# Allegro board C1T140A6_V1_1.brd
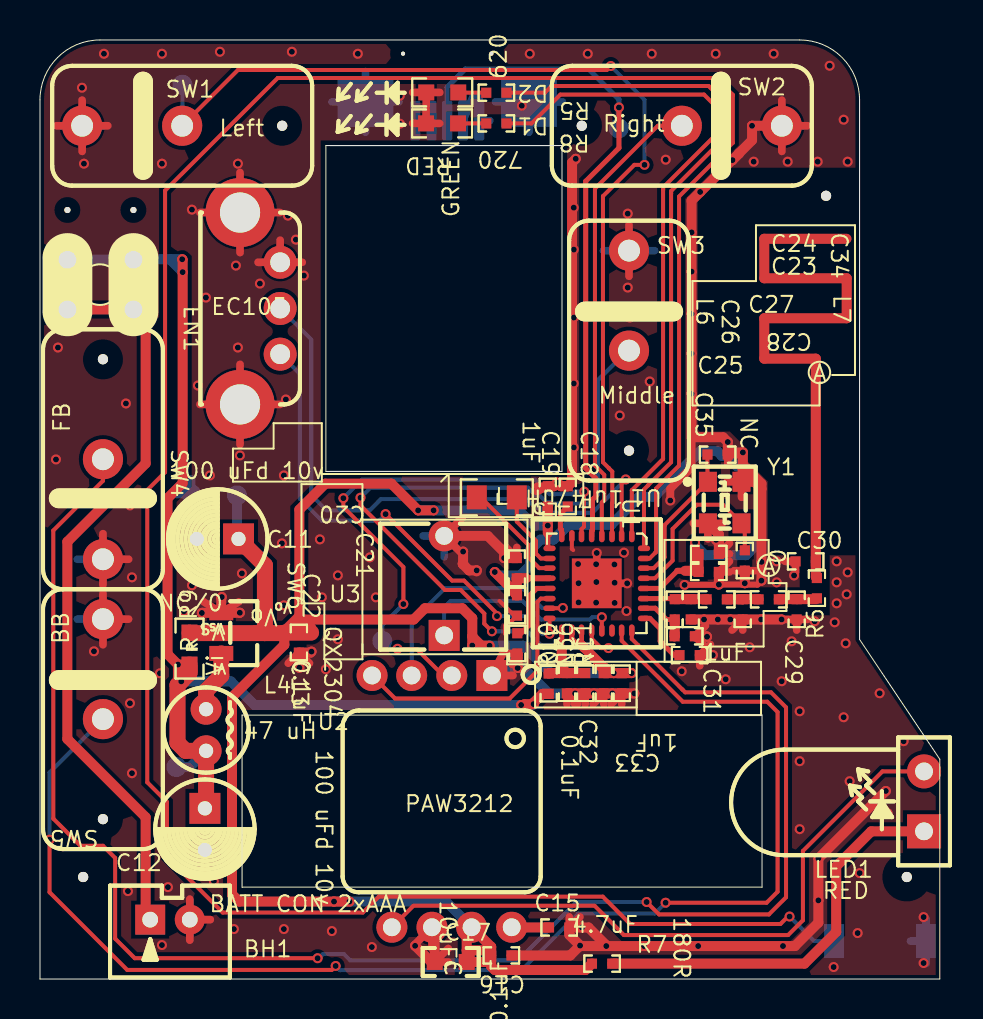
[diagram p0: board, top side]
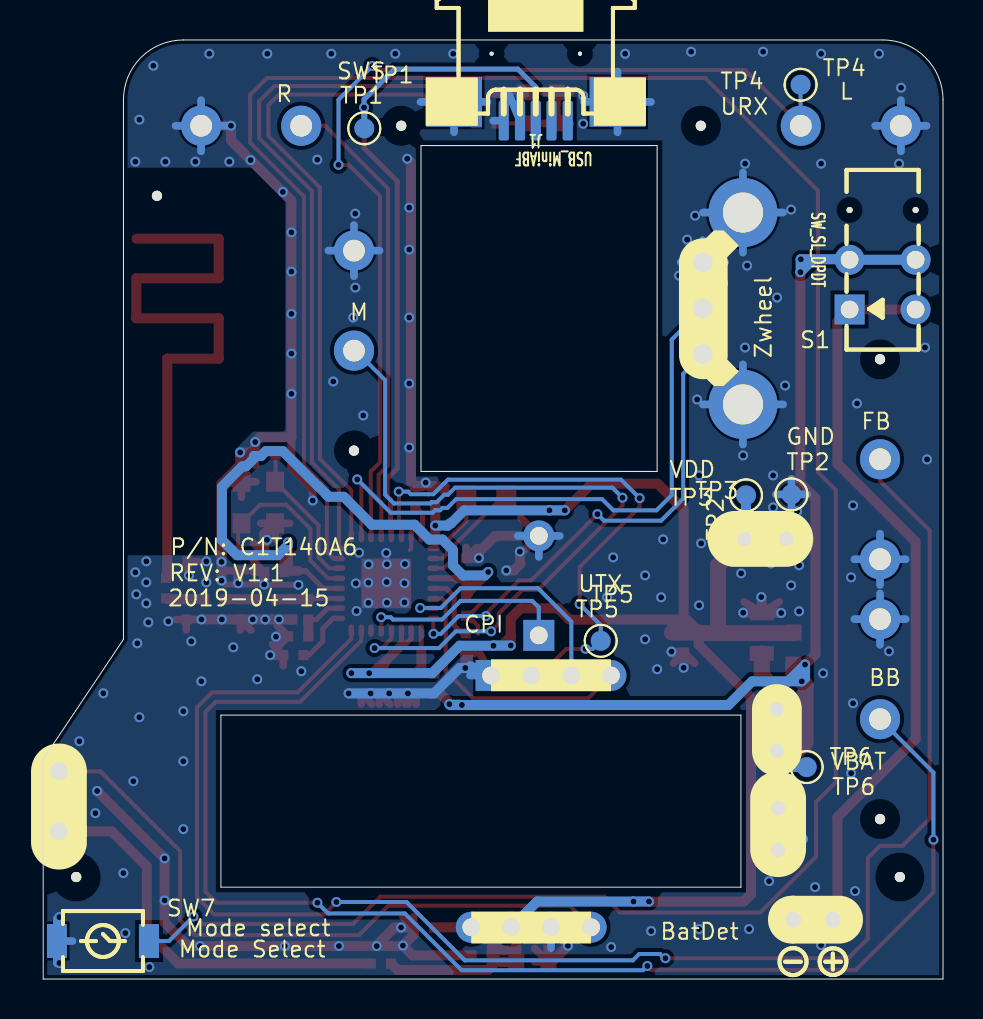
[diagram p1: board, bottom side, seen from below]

Outline 45.01 x 46.99 mm; copper layers: TOP, BOTTOM. Coordinates in mm from the lower left corner of the outline.
Outline path: 14.5,41.71 25.7,41.71 ; 25.91,25.4 14.5,25.4 ; 0,43.99 arc(0.88,46.11) 3,46.99 38,46.99 arc(40.12,46.11) 41,43.99 41,16.99 45.01,11 45.01,0 0,0 0,43.99 ; 10.11,13.21 36.12,13.21 36.12,4.6 10.11,4.6 10.11,13.21 ; 14.3,41.71 26.11,41.71 26.11,25.4 14.3,25.4 14.3,41.71

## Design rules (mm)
nets with their own width: nets AVDD GND LED N14408943 N14492061 VBAT ZWHEEL1 ZWHEEL2

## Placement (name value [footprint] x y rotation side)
BH1  BATT CON 2xAAA  [BATT-HDR200F-2PIN]  6.5 2.97 180 top
C11  100 uFd 10v  [C-100UF10V-ELECT]  8.89 22.02 180 top
C12  100 uFd 10v  [C-100UF10V-ELECT]  8.25 7.5 270 top
C13  0.1uF  [0402]  12.95 16.84 270 top
C15  4.7uF  [0402]  25.97 2.58 0 top
C16  0.1uF  [0402]  23.08 1.18 0 top
C17  10uF  [0603C]  20.54 0.85 180 top
C18  1uF  [0402]  26.4 24.15 270 top
C19  1uF  [0402]  25.4 24.15 270 top
C20  0.1uF  [0402]  23.85 20.56 270 top
C21  1uF  [0402]  23.86 18.69 90 top
C22  1uF  [0402]  23.87 16.79 90 top
C23  0.1uF  [0402]  33.45 20.37 0 top
C24  2.2uF  [0402]  33.45 21.27 0 top
C25  18pF  [0402]  32.25 17.15 180 top
C26  1.2pF  [0402]  32.55 18.5 270 top
C27  220pF  [0402]  33.85 19 180 top
C28  1.8pF  [0402]  35.15 18.5 270 top
C29  2.7pF  [0402]  37.85 18.5 270 top
C30  1pF  [0402]  38.3 20.9 180 top
C31  1uF  [0402]  32.49 16.21 180 top
C32  0.1uF  [0402]  28.2 14.8 90 top
C33  1uF  [0402]  29.1 14.8 90 top
C34  NC  [0402]  35.25 20.94 90 top
C35  NC  [0402]  33.9 26.24 0 top
C36  NC  [0402]  26.36 14.8 90 top
D1  GREEN  [0603-LED]  20.11 42.82 180 top
D2  RED  [0603-LED]  20.12 44.36 180 top
EN1  EC10E  [ENCODER-BTC-MOUSE]  12.01 35.87 90 top
J1  USB_MiniABF  [HIROSE-US60-MB-5ST_MINIUSB_7PIN]  20.37 52.3 0 bottom
L4  47 uH  [L-TH-IND2MM]  8.31 12.46 90 top
L5  47uH  [0805L]  22.85 24.1 0 top
L6  1.3nH  [0402]  31.75 18.5 90 top
L7  1.8nH  [0402]  36.45 19 0 top
LED1  RED  [LED_TH_3MM_2PIN]  44.22 8.89 90 top
NOREF  -  [unnamed]  43.36 5.11 0 top
NOREF#2  -  [unnamed]  2.16 5.11 0 top
NOREF#3  -  [unnamed]  39.32 39.19 0 top
R5  620  [0402]  22.83 44.35 0 top
R6  0  [0402]  38.86 19.56 90 top
R7  180R  [0402]  28.12 0.77 0 top
R8  720  [0402]  22.83 42.82 0 top
R9  NC/0  [0603R]  7.48 16.54 90 top
R10  0  [0402]  25.44 14.78 90 top
R11  NC  [0402]  27.27 14.8 270 top
S1  SW_SL_DPDT  [SW-TH-6PIN-3_60X9_00-34NP]  3.02 35.99 270 bottom
SW1  Left  [SW-CHICONY-MOUSE-3PIN-TH-3NP]  2.11 42.7 0 top
SW2  Right  [SW-CHICONY-MOUSE-3PIN-TH-3NP]  37.11 42.7 180 top
SW3  Middle  [SW-CHICONY-MOUSE-3PIN-TH-3NP]  29.46 36.45 270 top
SW4  FB  [SW-CHICONY-MOUSE-3PIN-TH-3NP]  3.15 21.01 90 top
SW5  BB  [SW-CHICONY-MOUSE-3PIN-TH-3NP]  3.15 18.01 270 top
SW6  CPI  [SW-MOUSE-2PIN-TH]  20.22 19.68 90 top
SW7  Mode select  [BUTSMD2PX4_00Y3_00_NH]  42.02 1.9 270 bottom
TP1  SWS  [TP100]  28.95 42.57 180 bottom
TP2  GND  [TP100]  7.58 24.25 180 bottom
TP3  VDD  [TP100]  9.86 24.2 180 bottom
TP4  URX  [TP100]  7.12 44.75 180 bottom
TP5  UTX  [TP100]  17.12 16.92 180 bottom
TP6  BatDet  [TP100]  6.82 10.61 180 bottom
U1  TLSR8258F512ET32  [QFN_5X5_32PIN_0P5_2P50X2P50]  27.85 19.8 270 top
U2  PAW3212  [SDIP8-ADNS5030]  20.6 8.89 180 top
U3  QX2304  [QX2304_SOT-23]  10.16 17.31 270 top
Y1  24MHz-12pF-+/-20ppm  [OSCCC200X250X080]  34.25 23.84 0 top

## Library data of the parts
BH1 = Chicony Battery conn 2xAA: User Part Number: pn; Tolerance: RichardLC
C11 C12 = 100 uFd Electrolytic 10v: User Part Number: partnum; Tolerance: RichardLC
C13 C16 = C1005X5R1C104K
C15 C18-C36 = C1005X5R1C105K
C17 = C1608X5R0J106M
D1 = 0603D_Green
D2 = 0603D_Red
EN1 = EC10E
J1 = USB_MiniABF_0: Tolerance: RichardLC; User Part Number: pn
L4 = 27 uH Inductor TH: User Part Number: partnum; Tolerance: RichardLC
L5-L7 = MLK1608_000R
LED1 = LED_5: User Part Number: partnum; Tolerance: RichardLC
R5 R6 R8 = RS0402K621JT
R7 R10 R11 = RS0402K181JT
R9 = RS0402K_34.8K_1%
S1 = SW_SL_DPDT: User Part Number: pn; Tolerance: RichardLC
SW1-SW5 = Switch Chicony Mouse 3PIN TH
SW6 = Switch Mouse Button 2PIN: Tolerance: RichardLC; User Part Number: partnum
SW7 = SW2PIN_3x4
TP1-TP6 = TestPad100
U1 = TLSR8258F512ET32
U2 = PAN3204UL
U3 = QX2304_SOT-23
Y1 = CRYSTAL4/SM_0

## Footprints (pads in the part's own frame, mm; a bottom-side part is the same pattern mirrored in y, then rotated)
0402
  rect 0.508x0.508 smd: 1(-0.508,0) 2(0.508,0)
0603-LED
  rect 0.8x0.8 smd: A(-0.8,0) C(0.8,0)
0603C
  rect 0.8x0.8 smd: 1(-0.8,0) 2(0.8,0)
0603R
  rect 0.8x0.8 smd: 1(-0.8,0) 2(0.8,0)
0805L
  rect 1x1.2 smd: 1(-1,0) 2(1,0)
BATT-HDR200F-2PIN
  rect 1.499x1.499 hole 0.787: 1(0.991,0)
  round 1.499 hole 0.787: 2(-0.991,0)
BUTSMD2PX4_00Y3_00_NH
  rect 1.7x1 smd: 1(0,2.3) 2(0,-2.3)
C-100UF10V-ELECT
  rect 1.549x1.549 hole 0.711: 1(-1.041,0)
  round 1.549 hole 0.711: 2(1.041,0)
ENCODER-BTC-MOUSE
  round 1.651 hole 0.991: 1(0,0) 2(-2.311,0) 3(-4.597,0)
  round 3.454 hole 2.007: 4(-7.112,2.007) 5(2.489,2.007)
HIROSE-US60-MB-5ST_MINIUSB_7PIN
  round 0.203 hole 0.889 unplated: (-2.21,5.994) (2.21,5.994)
  custom 0.127x0.127 smd: 1(-1.6,9.347) 2(-0.787,9.347) 3(0,9.347) 4(0.787,9.347) 5(1.6,9.347)
  rect 2.794x2.489 smd: 6(-4.089,8.407) 9(4.089,8.407)
L-TH-IND2MM
  round 1.549 hole 0.711: 1(-1.041,0) 2(1.041,0)
LED_TH_3MM_2PIN
  rect 1.702x1.702 hole 0.889: 1(-1.499,0)
  round 1.702 hole 0.889: 2(1.499,0)
OSCCC200X250X080
  rect 0.9x1 smd: 1(-0.84,1.04) 2(-0.84,-1.04) 3(0.84,-1.04) 4(0.84,1.04)
QFN_5X5_32PIN_0P5_2P50X2P50
  oval 0.61x0.279 smd: 1(-2.362,1.753) 2(-2.362,1.245) 3(-2.362,0.762) 4(-2.362,0.254) 5(-2.362,-0.254) 6(-2.362,-0.762) 7(-2.362,-1.245) 8(-2.362,-1.753) 17(2.362,-1.753) 18(2.362,-1.245) 19(2.362,-0.762) 20(2.362,-0.254) 21(2.362,0.254) 22(2.362,0.762) 23(2.362,1.245) 24(2.362,1.753)
  oval 0.279x0.61 smd: 9(-1.753,-2.362) 10(-1.245,-2.362) 11(-0.762,-2.362) 12(-0.254,-2.362) 13(0.254,-2.362) 14(0.762,-2.362) 15(1.245,-2.362) 16(1.753,-2.362) 25(1.753,2.362) 26(1.245,2.362) 27(0.762,2.362) 28(0.254,2.362) 29(-0.254,2.362) 30(-0.762,2.362) 31(-1.245,2.362) 32(-1.753,2.362)
  rect 2.489x2.489 smd: 33(0,0)
QX2304_SOT-23
  rect 0.75x1.2 smd: 1(-1.016,-1.092) 2(1.016,-1.092) 3(0,1.092)
SDIP8-ADNS5030
  rect 1.549x1.549 hole 0.889: 1(-2.007,-6.299)
  round 1.549 hole 0.889: 2(0,-6.299) 3(2.007,-6.299) 4(3.988,-6.299) 5(2.997,6.299) 6(0.991,6.299) 7(-0.991,6.299) 8(-2.997,6.299)
SW-CHICONY-MOUSE-3PIN-TH-3NP
  round 0.508 hole 1.092 unplated: (10.008,0)
  round 2.007 hole 1.092: 1(0,0) 2(5.004,0)
SW-MOUSE-2PIN-TH
  rect 1.549x1.549 hole 0.889: 1(-2.489,0)
  round 1.549 hole 0.889: 2(2.489,0)
SW-TH-6PIN-3_60X9_00-34NP
  round 0.305 hole 0.889 unplated: (-2.489,-1.651) (-2.489,1.651)
  rect 1.499x1.499 hole 0.889: 1(2.489,-1.651)
  round 1.499 hole 0.889: 2(0,-1.651) 5(0,1.651) 6(2.489,1.651)
TP100
  round 1 smd: 1(0,0)
unnamed
  round 0.508 hole 1.803 unplated: (0,0)

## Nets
AVDD: C11.1 C13.1 C16.1 C17.1 C19.2 C32.2 C33.2 R7.1 R9.2 TP3.1(TP) U1.9(VDD_IO) U1.18(VDD3) U1.19(VDDIO_AMS) U2.7(VDD) U3.3(VOUT)
GND: BH1.2(NEG) C11.2 C12.2 C13.2 C15.2 C16.2 C17.2 C18.1 C19.1 C20.1 C21.1 C22.1 C23.2 C24.2 C25.1 C26.2 C28.2 C29.2 C30.2 C31.1 C32.1 C33.1 C34.1 C35.2 C36.1 D1.C(CATHODE) D2.C(CATHODE) EN1.1(A) EN1.4(CASE1) EN1.5(CASE2) J1.4(ID) J1.5(GND) J1.6(S1) J1.9(S4) R11.2 SW1.1 SW2.1 SW3.1 SW4.1 SW5.1 SW6.2 SW7.2 TP2.1(TP) U1.7(DVSS) U1.33(GND) U2.1(OSC) U2.6(GND) U3.1(VSS) Y1.2 Y1.4
VBAT: C12.1 L4.1 R9.1 R10.1 S1.2 S1.5 TP6.1(TP)
LED: LED1.2(CATHODE) U2.5(LED)
TL_1V2: C20.2 C21.2 C23.1 C24.1 U1.12(VDD1V2) U1.28(AVDD1V2)
TL_ANT: C26.1 C27.2 L6.2 U1.27(ANT)
TL_BB: SW5.2 U1.23(P1/URX/I2C_SCK/32KIN/C[3])
TL_CPI: SW6.1 U1.21(I2C_SCK/P1N/P0/C[1])
TL_FB: SW4.2 U1.24(P2/UCTS/P0N/BIAS/C[4])
TL_LED_2.4G: R5.2 U1.32(P1N/I2S_SDI/7816_TRX/D[3])
TL_LED_BLE: R8.2 U1.1(SWM/I2S_SDO/P2N/D[4])
TL_LEFT: SW1.2 TP4.1(TP) U1.3(DMIC_DI/P0N/URX/A[0])
TL_MIDDLE: SW3.2 U1.20(I2C_SDA/P4N/URTS/C[0])
TL_MODE_SELECT: SW7.1 U1.31(CN/I2S_LR/P3/D[2])
TL_MOTION: TP5.1(TP) U1.6(P4/UTX/ATSEL2/B[1]) U2.2(MOV)
TL_RIGHT: SW2.2 U1.4(DMIC_CLK/7816_CLK/I2S_CLK/A[1])
TL_SCLK: U1.14(SDMP0/P4/B[4]) U2.4(SCLK)
TL_SDIO: U1.15(SDMN0/P5/B[5]) U2.3(SDOI)
TL_SWS: J1.3(D+) TP1.1(TP) U1.5(SWS/URTS/A[7])
TL_VANT: C25.2 L6.1 U1.26(VANT)
TL_XC1: C34.2 U1.29(XC1) Y1.3
TL_XC2: C35.1 U1.30(XC2) Y1.1
ZWHEEL1: EN1.3(C) U1.16(SDMP1/DI/URTS/B[6])
ZWHEEL2: EN1.2(B) U1.2(CK/I2S_BCK/7816_TRX/D[7])
N14408857: BH1.1(POS) S1.1 S1.6
N14408943: L4.2 U3.2(LX)
N14411039: C15.1 U2.8(VDDA)
N14476907: D2.A(ANODE) R5.1
N14481124: C36.2 R10.2 R11.1 U1.17(SDMN1/DO/URX/B[7])
N14481825: C18.2 U1.8(VDD1V)
N14482264: L5.2 U1.10(VDCDC_SW)
N14482268: L5.1 U1.11(VDCDC)
N14482755: C22.2 U1.13(VDD_F)
N14484292: C27.1 C28.1 L7.1
N14484500: C29.1 L7.2 R6.1
N14484554: C30.1 R6.2
N14485960: C31.2 U1.25(RESETB)
N14489122: D1.A(ANODE) R8.1
N14492061: LED1.1(ANODE) R7.2

Pads without a net: J1 1 2; U1 22

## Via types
v1: diameter 0.5, hole 0.3, TOP to BOTTOM, 211 vias

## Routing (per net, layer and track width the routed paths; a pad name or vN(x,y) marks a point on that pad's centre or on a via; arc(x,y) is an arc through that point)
AVDD: length 109.2
  TOP w0.25: 27.15,16.81 27.15,16.49 ; 27.15,16.81 27.09,16.81 ; 27.15,16.81 27.55,16.41 ; 27.15,16.49 27.55,16.08 ; 27.15,16.49 26.82,16.81 ; 27.82,15.81 28.2,15.43 C32.2 28.1,15.41 ; 27.82,15.81 27.82,15.73 27.85,15.7 27.85,15.66 28.1,15.41 ; 27.82,15.81 27.55,16.08 ; 28.1,15.41 28.1,15.86 ; 25.4,22.33 25.4,21.64 U1.9 ; v1(28.7,15.31) 28.34,15.67 28.29,15.67 28.1,15.86 ; 27.09,16.81 U1.19 ; 27.09,16.81 26.82,16.81 ; 28.1,15.86 27.55,16.41 ; 26.82,16.81 26.6,17.03 U1.18 ; 27.55,16.41 27.55,16.08
  TOP w0.5: 12.97,18.15 12.97,23.49 14.27,24.79 17.58,24.79 v1(18.92,23.45) v1(19.69,23.45) ; 12.97,18.15 13.14,17.99 ; 12.97,18.15 12.95,18.13 ; v1(22.49,16.68) 22.09,16.68 ; 22.09,16.68 22.08,16.69 22.06,16.69 21.65,17.1 21.65,17.12 21.62,17.15 ; 22.09,16.68 21.63,16.68 v1(21.62,16.69) 21.62,17.15 ; C19.2 v1(25.4,22.69) 25.4,22.33 ; C16.1 22.57,1.61 ; C16.1 22.24,0.85 C17.1 21.34,1.44 ; C16.1 22.57,0.63 22.75,0.45 27.29,0.45 R7.1 ; 22.57,1.61 U2.7 21.34,2.35 21.34,1.44 ; 22.57,1.61 22.4,1.44 21.34,1.44 ; 13.14,17.99 13.56,17.57 13.56,17.33 13.54,17.35 C13.1 ; 13.14,17.99 18.69,17.99 19.26,18.55 21.12,18.55 21.62,18.05 21.62,17.15 ; C32.2 v1(28.7,15.31) C33.2 v1(29.59,15.31) ; 12.22,17.31 12.22,16.72 9.61,14.11 9.61,4.24 9.97,3.88 v1(14.71,3.88) v1(15.48,3.88) ; 12.22,17.31 12.91,17.31 C13.1 ; 12.22,17.31 12.22,17.4 12.95,18.13 ; C13.1 12.95,18.13
  TOP w0.8: U3.3 11.25,20.7 C11.1 ; U3.3 7.51,17.31 R9.2 ; U3.3 12.22,17.31 12.25,17.33 13.56,17.33
  BOTTOM w0.5: v1(29.59,15.31) v1(28.7,15.31) 25.55,15.31 24.18,16.68 v1(22.49,16.68) 22.48,16.69 v1(21.62,16.69) ; v1(18.92,23.45) v1(19.69,23.45) 23.96,23.45 24.61,22.8 24.67,22.8 24.77,22.69 v1(25.4,22.69) ; C11.1 9.86,22.1 TP3.1 ; U2.7 20.3,3.88 v1(15.48,3.88) v1(14.71,3.88)
GND: length 302.8
  TOP w0.2: U1.7 26.6,21.53 26.67,21.46 ; 22.99,18.92 23.73,18.18 C21.1 23.58,17.91 23.5,17.91 23.26,17.67 23.26,17.27 ; 23.37,16.38 23.46,16.29
  TOP w0.3: v1(32.24,19.72) 33.76,19.72 33.77,19.74 v1(33.96,19.74) 35.11,19.74 35.17,19.8 v1(35.25,19.8) 35.32,19.74 35.89,19.74 v1(36.09,19.94)
  TOP w0.381: 18.64,44.36 D2.C ; D2.C 19.32,43.69 ; D2.C 20,44.36 ; 34.49,20.37 C23.2 34.49,20.9 ; SW4.1 3.15,22.29 ; SW4.1 3.15,19.73 ; SW4.1 4.43,21.01 ; SW2.1 37.11,43.98 ; SW2.1 37.11,41.42 ; SW2.1 38.39,42.7 ; 23.32,21.59 C20.1 23.85,21.59 ; 37.32,17.99 C29.2 ; C29.2 37.85,17.46 ; C29.2 38.38,17.99 ; Y1.2 34.14,22.8 ; Y1.2 32.68,22.8 ; Y1.2 33.41,22.03 ; D1.C 19.99,42.82 ; D1.C 19.31,43.49 ; D1.C 18.64,42.82 ; 23.66,15.19 U2.1 23.13,16.24 ; 26.89,13.76 C36.1 26.36,13.76 ; 18.71,1.7 U2.6 19.61,1.54 ; 33.29,16.62 C25.1 33.29,17.68 ; 27.27,13.76 R11.2 26.74,13.76 ; 10.01,26.75 EN1.4 ; EN1.4 10.01,30.76 ; EN1.4 8,28.75 ; EN1.4 12.01,28.75 ; 29.46,37.73 SW3.1 29.46,35.17 ; 23.61,15.76 C22.1 ; C22.1 23.46,16.29 ; C22.1 23.87,15.76 ; 24.87,24.66 C19.1 24.87,24.39 ; 26.48,3.11 C15.2 27.01,3.11 ; 34.4,25.71 C35.2 34.93,26.24 ; 34.49,21.8 C24.2 34.49,21.27 ; BH1.2 8.52,2.97 ; BH1.2 7.49,4 ; BH1.2 7.49,1.95 ; 27.85,19.86 v1(27.85,21.32) ; 8.19,18.87 U3.1 9.95,18.87 ; SW5.1 3.15,19.29 ; SW5.1 3.15,16.73 ; SW5.1 4.43,18.01 ; 28.2,13.76 C32.1 27.67,13.76 ; 2.11,41.42 SW1.1 ; SW1.1 3.39,42.7 ; SW1.1 0.83,42.7 ; SW1.1 2.11,43.98 ; 8.25,5.41 C12.2 7.2,6.46 ; 28.57,13.76 C33.1 29.1,13.76 ; U1.33 v1(29.37,19.8) ; 34.62,17.46 C28.2 35.15,17.46 ; 7.85,23.07 C11.2 7.85,20.97 ; 35.79,20.44 C34.1 34.72,20.44 ; EN1.1 12.01,36.97 ; EN1.1 13.12,35.87 ; EN1.1 10.91,35.87 ; 20.42,1.53 C17.2 20.42,0.85 ; 37.79,20.37 C30.2 37.26,20.9 ; 33.53,16.74 C31.1 33,15.68 ; EN1.5 12.01,38.35 ; EN1.5 8,38.35 ; EN1.5 10.01,36.35 ; EN1.5 10.01,40.36 ; 21.11,21.28 SW6.2 21.11,23.07 ; 35.09,24.11 Y1.4 ; Y1.4 35.09,25.66 ; Y1.4 34.36,24.88 ; 13.48,15.8 12.95,16.33 12.42,15.8
  TOP w0.4: v1(31.53,23.94) 31.53,24.53 32.59,25.59 32.59,27.11
  TOP w0.5: v1(27.02,1.67) 26.52,1.18 C16.2 ; v1(27.02,1.67) 26.48,2.21 C15.2 v1(27.11,2.58) 27.43,2.58 28.33,1.69 v1(28.33,1.65) ; v1(27.02,1.67) 27.04,1.65 v1(28.33,1.65) ; v1(13.58,16.38) 13.53,16.33 12.95,16.33 12.95,15.6 v1(12.97,15.58) ; U3.1 9.99,18.33 v1(10,18.33) ; U3.1 8.11,18.33 v1(8.1,18.32) ; U3.1 9.07,19.09 v1(9.09,19.11) ; v1(37.09,17.99) v1(36.07,17.99) C28.2 v1(34.53,17.99) v1(33.91,17.99) v1(33.21,17.99) C26.2 ; 35.16,25.72 36.09,24.79 36.09,24.53 ; 35.16,25.72 v1(35.16,26.35) 34.51,26.35 C35.2 v1(34.4,26.87) 34.17,27.11 32.59,27.11 v1(32.59,29.28) v1(32.59,31.3) v1(32.59,33.28) v1(32.59,35.4) v1(32.59,37.36) 32.59,38.96 v1(33.02,39.38) 34.61,40.98 v1(34.64,40.98) 34.96,41.3 34.96,41.31 35.62,41.97 v1(35.62,42.7) SW2.1 ; 35.16,25.72 35.16,24.95 Y1.4 35.73,24.88 36.09,24.53 ; U1.33 27.85,19.83 ; U1.33 27.84,19.81 v1(26.94,19.81) ; U1.33 27.85,19.76 v1(26.94,18.85) ; 27.85,19.83 v1(26.92,20.77) ; 27.85,19.83 27.85,19.86 v1(28.73,20.74) ; v1(28.74,18.82) 27.85,19.72 27.85,19.49 27.82,19.46 v1(27.82,18.83) ; C24.2 33.96,21.83 ; 33.96,21.83 v1(33.82,21.97) ; 33.96,21.83 33.96,22.25 Y1.2 ; 21.84,20.4 21.84,20.45 ; v1(26.8,41.04) 26.61,40.86 26.61,25.04 26.6,25.03 26.6,24.86 C18.1 26.06,24.66 v1(25.88,24.84) 25.7,24.66 C19.1 ; U2.6 19.74,2.45 C17.2 19.57,0.85 v1(18.76,1.66) ; C23.2 v1(33.96,19.74) ; v1(21.84,20.45) 21.46,20.45 21.15,20.76 21.15,20.8 21.17,20.81 v1(21.17,21.39) ; v1(42.31,9.41) v1(38.94,6.03) v1(38.94,3.94) 38.94,2.82 37.76,1.65 v1(37.16,1.65) v1(32.92,1.65) v1(30.21,1.65) v1(28.33,1.65) ; v1(36.09,19.94) v1(36.09,20.87) 36.09,24.53 ; C20.1 v1(23.22,21.06) 23.22,21.35 22.4,22.17 SW6.2 ; v1(33.37,17.13) 33.35,17.15 C25.1 ; C31.1 v1(33.66,16.21) ; C22.1 23.9,16.26 v1(23.9,15.56) ; v1(29.73,14.29) C33.1 v1(28.63,14.29) C32.1 28.2,14.29 v1(27.71,14.29) R11.2 v1(26.77,14.29) C36.1 ; v1(35.25,19.8) C34.1
  BOTTOM w0.381: 37.11,41.42 SW2.1 ; SW2.1 38.39,42.7 ; SW2.1 37.11,43.98 ; SW2.1 35.83,42.7 ; TP2.1 8.36,24.25 ; TP2.1 7.58,23.47 ; TP2.1 6.8,24.25 ; TP2.1 7.58,25.03 ; 22.5,42.95 J1.5 21.97,44.22 ; EN1.5 10.01,40.36 ; EN1.5 10.01,36.35 ; EN1.5 8,38.35 ; EN1.5 12.01,38.35 ; 7.49,1.95 BH1.2 ; BH1.2 8.52,2.97 ; BH1.2 7.49,4 ; 3.15,19.73 SW4.1 ; SW4.1 1.87,21.01 ; SW4.1 3.15,22.29 ; SW4.1 4.43,21.01 ; EN1.4 12.01,28.75 ; EN1.4 10.01,30.76 ; EN1.4 8,28.75 ; EN1.4 10.01,26.75 ; 28.18,36.45 SW3.1 ; SW3.1 30.74,36.45 ; SW3.1 29.46,35.17 ; SW3.1 29.46,37.73 ; 23.66,15.19 U2.1 23.66,15.71 ; 18.71,1.7 U2.6 19.61,1.54 ; 7.2,6.46 C12.2 ; C12.2 9.3,6.46 ; C12.2 8.25,5.41 ; 0.83,42.7 SW1.1 ; SW1.1 2.11,41.42 ; SW1.1 2.11,43.98 ; SW1.1 3.39,42.7 ; 44.32,1.9 44.32,3.03 ; 44.32,1.9 43.54,1.9 ; 44.32,1.9 44.32,0.77 ; 7.85,20.97 C11.2 ; C11.2 6.8,22.02 ; C11.2 7.85,23.07 ; SW6.2 21.27,22.17 ; SW6.2 19.17,22.17 ; SW6.2 20.22,21.12 ; EN1.1 12.01,36.97 ; EN1.1 13.12,35.87 ; EN1.1 10.91,35.87 ; 3.15,16.73 SW5.1 ; SW5.1 4.43,18.01 ; SW5.1 1.87,18.01 ; SW5.1 3.15,19.29 ; 21.16,44.22 J1.4 21.69,44.22 ; J1.6 17.96,43.89 ; J1.6 16.28,45.41 ; J1.6 14.61,43.89 ; J1.6 16.28,42.37 ; 22.79,43.89 J1.9 ; J1.9 24.46,42.37 ; J1.9 26.13,43.89
  BOTTOM w0.5: v1(29.73,14.29) v1(28.63,14.29) 28.63,14.29 v1(27.71,14.29) v1(26.77,14.29) 25.46,14.29 24.74,15.01 24.74,15.01 24.19,15.56 v1(23.9,15.56) 22.98,15.56 U2.1
  vias: v1(0.8,26) v1(0.9,31.6) v1(2.1,44.6) v1(2.2,40.8) v1(2.7,16.4) v1(3.2,46.3) v1(4.3,28.8) v1(4.4,4.4) v1(4.5,23.7) v1(4.5,13.8) v1(4.6,20.1) v1(4.6,10.3) v1(6,15.3) v1(6.1,46.3) v1(6.1,40.8) v1(6.1,1.7) v1(6.4,4.6) v1(7,7) v1(7.2,20.7) v1(7.2,18.4) v1(7.3,23.4) v1(7.6,38.5) v1(7.6,19.7) v1(7.9,29.7) v1(8.3,34.1) v1(8.5,25.2) v1(8.5,23.6) v1(8.6,20.8) v1(8.7,4.9) v1(9,46.4) v1(9.7,2.5) v1(9.8,35.7) v1(9.9,40.8) v1(9.9,31.6) v1(10,26.2) v1(10.1,20.3) v1(11,34.8) v1(12.1,21.8) v1(12.2,25.2) v1(12.2,18.7) v1(12.2,2.5) v1(12.3,29) v1(12.4,38.2) v1(12.6,46.4) v1(12.8,37) v1(13.2,35.2) v1(14,22) v1(14.1,19.1) v1(14.3,15.5) v1(14.6,2.4) v1(14.9,20.2) v1(14.9,17) v1(15.9,46.3) v1(16.5,21.1) v1(16.6,1.6) v1(16.8,19.1) v1(18,44.2) v1(18,42.8) v1(24.1,43.7) v1(24.5,46.3) v1(26.7,38.6) v1(26.7,36.5) v1(26.7,33.1) v1(26.7,29.8) v1(26.7,26.6) v1(27.4,46.3) v1(27.82,20.76) v1(27.83,19.87) v1(28.74,19.83) v1(29,28.2) v1(29.21,21.34) v1(29.34,18.41) v1(29.4,38.3) v1(29.4,34.6) v1(29.5,33.1) v1(30.5,29.9) v1(30.6,46.3) v1(31.3,41) v1(32.1,15.4) v1(33.8,46.3) v1(34.3,15) v1(35.5,16.6) v1(35.7,40.9) v1(36.7,46.3) v1(36.85,20.9) v1(36.85,19.85) v1(37.1,14.9) v1(37.4,40.9) v1(37.6,16.9) v1(37.72,20.19) v1(38,13.4) v1(38,10.9) v1(38,7.5) v1(38.75,17.9) v1(38.9,40.9) v1(39.5,45.7) v1(39.7,0.6) v1(39.75,17.85) v1(39.85,20.9) v1(39.85,19.85) v1(39.85,18.8) v1(40.2,43) v1(40.2,13.1) v1(40.3,16.8) v1(40.4,40.9) v1(40.4,20.35) v1(40.35,19.25) v1(40.5,9.9) v1(40.9,2.3) v1(41,5.3) v1(42,14.3) v1(42.4,8.3) v1(43.2,11.9) v1(44.2,3.1) v1(44.2,0.8)
VBAT: length 61.9
  TOP w0.5: v1(7.11,36.02) 7.14,35.99 v1(7.14,35.37) 7.14,24.81 6.38,24.06 6.38,16.26 v1(6.9,15.73) ; v1(24.07,13.71) 24.2,13.71 24.24,13.75 24.61,13.75 24.62,13.76 v1(24.69,13.76) 24.69,13.83 25.14,14.27 R10.1 ; v1(6.9,15.73) 6.9,15.06 v1(7.07,14.9) ; v1(6.9,15.73) R9.1
  TOP w0.8: R9.1 7.48,15.31 v1(7.07,14.9) 6.88,14.71 6.88,11.82 7.28,11.42 L4.1 8.31,8.6 C12.1
  BOTTOM w0.5: 7.11,35.4 v1(7.11,36.02) 6.53,36.02 ; 7.11,35.4 6.53,35.98 6.53,36.02 ; 7.11,35.4 v1(7.14,35.37) ; 7.74,14.9 9.55,14.9 10.73,13.71 v1(24.07,13.71) 24.65,13.71 v1(24.69,13.76) ; 7.74,14.9 v1(7.07,14.9) 6.9,15.06 v1(6.9,15.73) 7.74,14.9 ; S1.5 S1.2 4.7,36.02 6.53,36.02 ; TP6.1 7.5,10.61 L4.1
LED: length 33.1
  TOP w0.2: 44.22,10.39 42.14,10.39 38.16,6.41 38.16,2.94 37.42,2.2 29.21,2.2 27.74,3.67 18.68,3.67 U2.5
TL_1V2: length 33.4
  TOP w0.25: 31.88,20.43 31,19.55 U1.28
  TOP w0.3: 32.27,20.43 31.88,20.43 ; 24.3,20.05 U1.12
  TOP w0.5: v1(32.77,21.84) 32.77,20.55 32.89,20.43 ; 32.89,20.43 C23.1 C24.1 ; 32.89,20.43 32.27,20.43 ; C21.2 23.85,19.21 ; 23.85,19.21 23.76,19.3 23.76,19.36 v1(22.75,20.37) ; 23.85,19.21 C20.2 23.86,20.05 24.3,20.05
  BOTTOM w0.5: v1(22.75,20.37) 22.92,20.19 24.01,20.19 24.51,20.69 24.51,21.46 25.04,21.99 25.69,21.99 26.43,22.73 28.57,22.73 29.97,24.13 30.73,24.13 30.83,24.22 30.83,24.23 31.24,24.64 31.25,24.64 33.02,26.42 33.87,26.42 34.11,26.17 34.46,26.17 34.46,26.06 34.87,25.65 35.05,25.65 36.07,24.64 36.07,21.96 35.31,21.21 33.27,21.21 32.77,21.71 v1(32.77,21.84)
TL_ANT: length 3.1
  TOP w0.25: U1.27 31.72,19.04 L6.2
  TOP w0.5: L6.2 C26.1 33.33,19.01 C27.2
TL_BB: length 68.4
  TOP w0.2: v1(31.29,3.82) 36.34,3.82 36.9,4.37 36.9,13.36 36.38,13.88 32.15,13.88 29.09,16.93 U1.23 ; v1(0.48,6.97) 0.48,4.34 4.36,0.45 14.59,0.45 v1(14.79,0.65)
  BOTTOM w0.2: v1(31.29,3.82) 30.75,3.28 26.92,3.28 24.08,0.44 15,0.44 v1(14.79,0.65) ; SW5.2 0.48,10.33 v1(0.48,6.97)
TL_CPI: length 10.5
  TOP w0.2: v1(28.1,18.11) 28.1,18.06 U1.21
  BOTTOM w0.2: SW6.1 20.22,18.6 20.55,18.92 24.13,18.92 25.06,17.99 27.51,17.99 27.63,18.11 v1(28.1,18.11)
TL_FB: length 82
  TOP w0.2: v1(30.34,3.85) 30.96,3.23 36.46,3.23 37.32,4.09 37.32,13.59 36.57,14.34 32.28,14.34 32.14,14.48 32.14,14.48 29.92,16.7 29.92,16.7 29.6,17.02 U1.24 ; SW4.2 3.15,24.93 0.67,22.44 0.67,8.03 2.03,6.67 3.15,6.67 3.76,6.06 3.76,2.02 4.74,1.04 v1(13.89,1.04)
  BOTTOM w0.2: v1(13.89,1.04) 13.95,1.04 14.16,1.25 15.2,1.25 15.52,0.93 23.92,0.93 26.84,3.85 v1(30.34,3.85)
TL_LED_2.4G: length 35.4
  TOP w0.2: R5.2 25.26,44.35 25.59,44.69 33.44,44.69 34.21,43.92 34.21,42.08 31.57,39.44 31.57,39.32 31.57,39.32 31.57,25.86 30.42,24.71 30.42,24.7 30.21,24.5 U1.32
TL_LED_BLE: length 34.5
  TOP w0.2: U1.1 29.6,24.46 31.17,26.02 31.17,39.49 31.17,39.49 31.17,39.61 33.74,42.18 33.74,43.73 33.22,44.26 26.03,44.26 24.59,42.82 R8.2
TL_LEFT: length 50.3
  TOP w0.2: v1(28.55,45.69) 28.35,45.49 9.9,45.49 SW1.2 ; U1.3 28.61,23.8 28.63,23.81 28.63,25.39 28.46,25.56 28.16,25.86 28.16,39.17 29.73,40.74 v1(30.24,40.74)
  BOTTOM w0.2: v1(30.24,40.74) 30.24,44 v1(28.55,45.69) ; TP4.1 7.12,42.71 SW1.2
TL_MIDDLE: length 38
  TOP w0.2: v1(22.61,17.4) 22.23,17.78 22.23,18.29 21.05,19.47 20.26,19.47 16.03,23.7 v1(16.03,24.08) ; v1(28.43,16.56) 28.07,16.56 27.6,17.03 U1.20
  BOTTOM w0.2: v1(22.61,17.4) 24.37,17.4 25.21,16.56 v1(28.43,16.56) ; v1(16.03,24.08) 16.53,24.59 24.41,24.59 24.76,24.24 24.95,24.24 25.32,23.86 25.57,23.86 25.64,23.8 27.47,23.8 27.9,24.24 27.9,29.97 29.38,31.45 SW3.2
TL_MODE_SELECT: length 126.5
  TOP w0.2: U1.31 30.49,21.04 30.78,21.34 30.82,21.37 30.82,24.54 31.97,25.69 31.97,39.16 34.66,41.85 34.66,44.24 33.81,45.09 24.69,45.09 11.89,45.09 6.26,39.45 6.26,25.36 5.37,24.47 5.37,9.84 6.35,8.86 6.35,6.11 9.14,3.33 16.15,3.33 16.95,4.12 28.15,4.12 29.52,2.75 37.04,2.75 37.41,3.13 v1(37.49,3.13)
  BOTTOM w0.2: v1(37.49,3.13) 38.72,1.9 SW7.1
TL_MOTION: length 28.1
  TOP w0.2: v1(27.23,24.39) 27.21,24.38 27.21,22.64 27.09,22.51 U1.6 ; v1(18.18,18.76) 18.18,20.61 15.18,23.62 v1(15.18,24.06) ; U2.2 20.17,15.19 18.84,16.51 17.9,16.51 v1(17.88,16.52)
  BOTTOM w0.2: v1(15.18,24.06) 16.1,24.99 24.76,24.99 24.95,24.8 25.49,24.26 25.74,24.26 26.62,24.26 26.75,24.39 v1(27.23,24.39) ; v1(17.88,16.52) 17.52,16.52 TP5.1 17.12,17.71 v1(18.18,18.76)
TL_RIGHT: length 23.3
  TOP w0.2: 32.1,42.7 30.91,42.7 27.76,39.55 27.76,25.69 28.23,25.23 28.23,23.97 28.1,23.85 U1.4
TL_SCLK: length 13.4
  TOP w0.2: U2.4 17.76,14.04 23.5,14.04 24.88,15.42 24.88,18.87 25.05,19.04 U1.14
TL_SDIO: length 12
  TOP w0.2: v1(26.16,18.57) 26.12,18.57 26.1,18.55 U1.15
  BOTTOM w0.2: U2.3 18.59,17.89 20.26,19.56 24.13,19.56 25.12,18.57 v1(26.16,18.57)
TL_SWS: length 35.2
  TOP w0.25: U1.5 27.6,22.42 27.64,22.46 27.64,23.99 27.8,24.15 27.8,25.05 27.3,25.56 27.3,39.92 28.96,41.59 v1(28.96,43.61)
  BOTTOM w0.25: v1(28.96,43.61) 28.96,44.01 27.44,45.53 21.27,45.53 20.36,44.62 20.36,42.97 J1.3
  BOTTOM w0.3: v1(28.96,43.61) 28.95,43.6 TP1.1
TL_VANT: length 2.6
  TOP w0.25: U1.26 30.78,18.55 31.34,17.99 L6.1
  TOP w0.5: C25.2 31.75,17.16 L6.1
TL_XC1: length 9.1
  TOP w0.2: C34.2 35.25,22.64 Y1.3 34.16,23.73 32.86,23.73 31.64,22.52 31.64,20.94 30.76,20.05 U1.29
TL_XC2: length 7.3
  TOP w0.2: U1.30 30.7,20.56 31.24,21.11 31.24,22.69 31.25,22.69 31.25,22.72 Y1.1 33.39,24.91 C35.1
ZWHEEL1: length 24
  TOP w0.2: v1(22.86,18.16) 22.86,18.29 21.21,19.94 20.62,19.94 v1(17.29,23.26) ; U1.16 v1(25.49,17.27)
  BOTTOM w0.2: v1(25.49,17.27) 25.12,17.27 24.23,18.16 v1(22.86,18.16) ; EN1.3 13,30.29 13,24.04 14.1,22.94 16.96,22.94 v1(17.29,23.26)
ZWHEEL2: length 30.2
  TOP w0.2: v1(29.3,25) 29.09,24.79 U1.2
  BOTTOM w0.2: EN1.2 13.57,32 13.57,24.21 14.33,23.45 16.49,23.45 17.05,24.02 24.35,24.02 24.79,23.57 25.04,23.57 25.16,23.46 25.41,23.46 25.53,23.33 27.63,23.33 29.29,25 v1(29.3,25)
N14408857: length 37.4
  TOP w0.5: BH1.1 5.28,3.2 5.28,8.1 1.37,12.01 1.37,21.88 5.28,25.8 5.28,32.89 S1.1 S1.6
N14408943: length 3.1
  TOP w0.8: U3.2 9.07,15.19 8.31,14.43 8.31,13.5
N14411039: length 1.9
  TOP w0.5: U2.8 23.61,2.58 C15.1
N14476907: length 1.4
  TOP w0.2: D2.A 20.93,44.35 R5.1
N14481124: length 4.4
  TOP w0.25: 26.1,16.43 U1.17
  TOP w0.5: C36.2 25.99,15.31 ; C36.2 R11.1 ; C36.2 26.1,15.57 ; 25.99,15.31 26.1,15.42 26.1,15.57 ; 25.99,15.31 25.47,15.31 R10.2 ; 26.1,15.57 26.1,16.43
N14481825: length 1.7
  TOP w0.25: C18.2 26.03,23.27 26.03,22.54 26.09,22.48 26.09,22.17 U1.8
N14482264: length 4
  TOP w0.2: L5.2 23.85,22.89 24.81,21.93 24.81,21.29 25.05,21.04 U1.10
N14482268: length 5.5
  TOP w0.2: U1.11 24.97,20.56 24.41,21.12 24.41,21.74 22.05,24.1 L5.1
N14482755: length 3.4
  TOP w0.25: U1.13 24.84,19.55 24.46,19.16 24.46,19.05 24.46,19.04 24.46,18.69 24.46,17.7 24.06,17.3 C22.2
N14484292: length 1.6
  TOP w0.5: C27.1 35.14,19 C28.1 35.93,19.01 L7.1
N14484500: length 1.9
  TOP w0.2: R6.1 38.86,19.05 38.82,19.01
  TOP w0.5: 38.82,19.01 C29.1 36.97,19.01 L7.2
N14484554: length 31.9
  TOP w0.5: 40.34,37.04 36.23,37.04 36.23,35.07 40.35,35.07 40.35,33.07 36.23,33.07 36.23,31.04 38.81,31.04 C30.1 38.81,20.12 R6.2
N14485960: length 2.9
  TOP w0.25: U1.25 30.51,18.05 31.02,17.53 31.02,16.9 31.72,16.21 C31.2
N14489122: length 1.4
  TOP w0.2: R8.1 D1.A
N14492061: length 20.3
  TOP w0.5: R7.2 38.24,0.77 39.83,2.35 39.83,5.64 41.58,7.39 LED1.1

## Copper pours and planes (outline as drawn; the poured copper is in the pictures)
GND on TOP: 0.2,0.2 0.2,43.99 1.02,45.97 3,46.79 38,46.79 39.97,45.97 40.79,43.99 40.79,40.6 34.6,40.6 32.9,38.9 32.9,27.5 33,27.4 34.5,27.4 35.4,26.5 35.4,25.9 36.4,24.9 36.4,21.2 38,21.2 38,19.6 29.6,19.6 29.6,18.2 39.5,18.2 39.5,21.2 40.79,21.2 40.79,16.94 44.81,10.95 44.81,0.2 ; 22 cut-outs
GND on BOTTOM: 0.2,0.2 0.2,43.99 1.02,45.97 3,46.79 38,46.79 39.97,45.97 40.79,43.99 40.79,40.6 34.6,40.6 32.9,38.9 32.9,27.5 33,27.4 34.5,27.4 35.4,26.5 35.4,25.9 36.4,24.9 36.4,21.2 40.79,21.2 40.79,16.94 41.61,15.71 44.81,10.95 44.81,0.2 ; 17 cut-outs

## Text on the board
Ref Des/Silkscreen Bottom: BB | FB | L | VBAT | GND | URX | VDD | BatDet | UTX | CPI | M | SWS | R | Mode Select | P/N: C1T140A6 | REV: V1.1 | 2019-04-15 | Zwheel
Ref Des/Silkscreen Top: A
COMPVAL_TYPE_TOP: 2019-04-15 | C1T140A6_V1.1
DISPLAY_TOP: FIGURE | SIZE | 0.3 | 0.711 | 0.787 | 0.889 | 0.991 | 1.092 | 2.007 | 1.803 | DRILL CHART: TOP to BOTTOM | ALL UNITS ARE IN MILLIMETERS | PLATED | NON-PLATED | QTY | 211 | 6 | 2 | 16 | 3 | 10 | 4 | 5
